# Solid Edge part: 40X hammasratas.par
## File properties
Author: Türk
Template: Iso Part.par
Last saved by: Türk
Revision: 5
Application: Solid Edge
Accuracy: 0,990
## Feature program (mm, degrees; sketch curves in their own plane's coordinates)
pattern "PatternOccurrence_1"  XOffset = 9 deg
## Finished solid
Body 1: solid body, 166 faces, 484 edges, 320 vertices.
  Faces by surface: plane 124, cylinder 42
  Edges by curve: line 400, circle 84
Bounding box of the edges (mm): 52.000 x 35.000 x 52.000, from (-26, 0, -26) to (26, 35, 26).
Cylindrical faces by radius (mm): R6 x2, R24 x40
Planar faces by outward normal: +x 1, +y 2, +z 1, -x 1, -y 2, -z 1, oblique 116
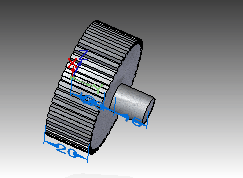
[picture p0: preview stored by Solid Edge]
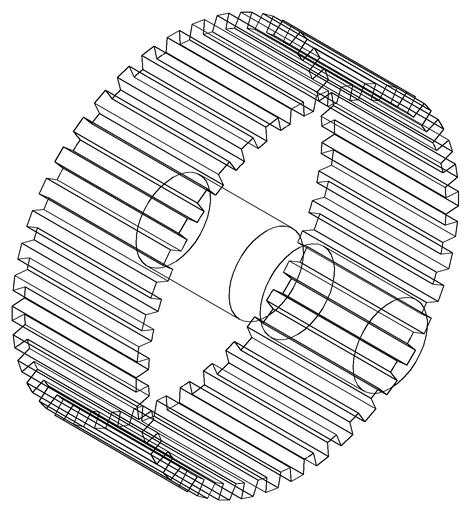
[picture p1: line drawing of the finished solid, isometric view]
